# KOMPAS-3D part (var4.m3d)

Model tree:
1. ВЗ
2. jcm
     Расстояние = 75
3. ВЗ 1
     Расстояние = 50
4. ВЗ 2
     Расстояние = 50
5. ВЗ 3
     Расстояние = 50
6. ВЗ 4
     Расстояние = 50
7. ВЗ 5
     Расстояние = 50
8. ВЗ 6
     Расстояние = 50
9. Эскиз:9
10. Операция выдавливания:4
     Расстояние 1 = 65; Расстояние 2 = 60
11. Эскиз:10
12. Операция выдавливания:5
     Расстояние 1 = 65; Расстояние 2 = 70
13. Булева операция:2
14. Эскиз:11
15. Операция выдавливания:6
     Расстояние 1 = 545; Расстояние 2 = 360
16. Булева операция:3
17. Зеркальное отражение:3
18. ВЗ 7
     Расстояние = 50
19. ВЗ  8
     Расстояние = 50
20. боковые понтоны
21. Эскиз:21
22. Правый киль
     Толщина стенки 1 = 1; Толщина стенки 2 = 1; Расстояние 1 = 7; Расстояние 2 = 360
23. Левый киль
24. Киль1
25. Эскиз:22
26. Операция выдавливания:9
     Расстояние 1 = 125; Расстояние 2 = 125
27. стабилизатор1
28. Эскиз:24
29. Операция выдавливания:10
     Расстояние 1 = 75; Расстояние 2 = 75
30. Эскиз:25
31. Эскиз:26
32. Эскиз:27
33. Эскиз:30
34. Операция по сечениям:1
     Толщина стенки 1 = 2; Толщина стенки 2 = 2
35. Эскиз:28
36. Кинематическая операция:6
     Толщина стенки 1 = 2; Толщина стенки 2 = 14
37. Эскиз:29
38. Операция выдавливания:11
     Расстояние 1 = 45; Расстояние 2 = 45
39. Булева операция:8
40. Кабина2
41. Корпус2
42. сопло
     Толщина стенки 1 = 2; Толщина стенки 2 = 2
43. турбина 2
44. сечение воздухозаборника
45. Смещенная плоскость:1
     Расстояние = 40
46. плоскости
47. траектория воздухозаборника
48. Кинематическая операция:10
     Толщина стенки 1 = 4; Толщина стенки 2 = 2
49. Кинематическая операция:13
     Толщина стенки 1 = 4; Толщина стенки 2 = 2
50. Булева операция:15
51. Зеркальное отражение:4
52. воздухозаборник
53. Эскиз:37
54. Эскиз:38
55. Эскиз:39
56. Кинематическая операция:14
     Толщина стенки 1 = 4; Толщина стенки 2 = 2
57. Операция по сечениям:4
     Толщина стенки 1 = 2; Толщина стенки 2 = 2
58. кабина
